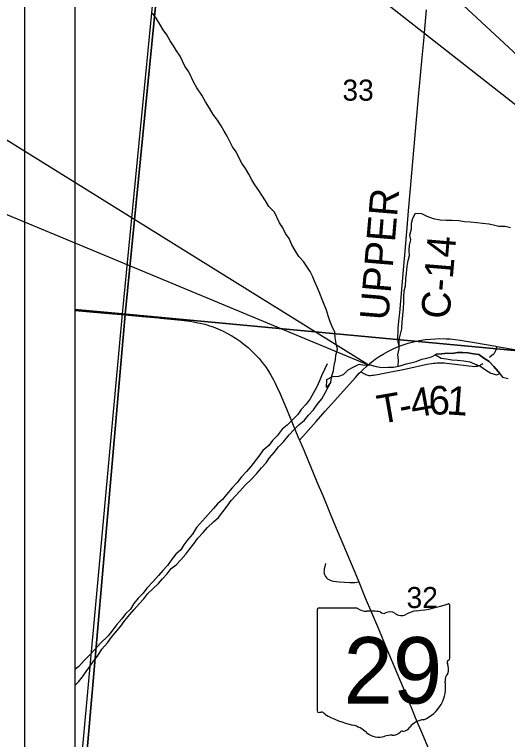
# Model space of a CAD drawing. Extents: x 831 to 1552, y 430 to 870.
# Drawn here: x 943.37 to 962.97, y 664.2 to 692.99 of the extents above; entities that cross this region are included whole.
import ezdxf

# ---------------------------------------------------------------- set-up
doc = ezdxf.new("R2010")
doc.units = 0
for name, color, linetype in [('GM_X_Corporation', 7, 'Continuous'), ('GM_X_County_Road', 7, 'Continuous'), ('GM_X_County_Road_Text', 7, 'Continuous'), ('GM_X_Major_River', 7, 'Continuous'), ('GM_X_Minor_Lake', 7, 'Continuous'), ('GM_X_Minor_River', 7, 'Continuous'), ('GM_X_Section_Text', 7, 'Continuous'), ('GM_X_State_Location', 7, 'Continuous'), ('GM_X_State_Route', 7, 'Continuous'), ('GM_X_State_Shield', 7, 'Continuous'), ('GM_X_Township_Road', 7, 'Continuous'), ('GM_X_Township_Road_Text', 7, 'Continuous'), ('SH_Data', 7, 'Continuous'), ('SH_Text', 7, 'Continuous')]:
    doc.layers.add(name, color=color, linetype=linetype)

msp = doc.modelspace()

# ---------------------------------------------------------------- linework, layer by layer
at = {"layer": 'GM_X_Corporation'}
msp.add_lwpolyline([(957.479, 781.045), (956.56, 771.006), (955.451, 760.717), (953.653, 740.871), (952.689, 730.885), (949.971, 703.401), (947.763, 681.071), (945.766, 658.183), (945.766, 650.938), (1069.909, 650.938), (1070.34, 654.531), (1072.813, 675.454), (1078.126, 715.958), (1081.227, 740.59), (1081.766, 744.853), (1081.766, 786.938)], dxfattribs=at)
for points in [[(945.766, 741.831), (945.766, 658.183), (947.763, 681.071), (949.971, 703.401), (952.689, 730.885), (953.653, 740.871)], [(945.766, 701.429), (945.766, 681.274), (947.656, 681.105), (949.612, 701.081)], [(970.228, 699.411), (968.2, 679.179), (947.656, 681.105), (949.612, 701.081)], [(945.766, 681.274), (945.766, 661.485), (945.863, 661.476), (947.656, 681.105)], [(947.656, 681.105), (968.2, 679.179), (966.669, 658.742), (945.863, 661.476)]]:
    msp.add_lwpolyline(points, close=True, dxfattribs=at)
at = {"layer": 'GM_X_County_Road'}
msp.add_lwpolyline([(958.663, 679.814), (958.644, 679.888), (958.633, 679.934), (958.623, 679.981), (958.615, 680.041), (958.61, 680.11), (958.607, 680.202), (958.614, 680.366), (958.625, 680.543), (958.66, 680.926), (958.681, 681.149), (958.72, 681.607), (958.833, 682.845), (958.897, 683.576), (958.94, 684.071), (958.98, 684.516), (959.037, 685.198), (959.116, 686.076), (959.195, 686.993), (959.313, 688.355), (959.435, 689.716), (959.511, 690.571), (959.576, 691.288), (959.636, 691.944), (959.689, 692.563), (959.744, 693.182)], dxfattribs=at)
at = {"layer": 'GM_X_Major_River'}
for points in [[(955.948, 678.394), (955.978, 678.644), (956.052, 678.84), (956.081, 679.053), (956.133, 679.272), (956.146, 679.462), (956.213, 679.696), (956.152, 679.926), (956.121, 680.163), (956.104, 680.369), (955.983, 680.631), (955.897, 680.824), (955.842, 681.023), (955.765, 681.246), (955.674, 681.478), (955.603, 681.677), (955.512, 681.916), (955.412, 682.132), (955.298, 682.402), (955.213, 682.595), (955.128, 682.787), (954.989, 682.982), (954.858, 683.184), (954.674, 683.387), (954.522, 683.62), (954.392, 683.844), (954.285, 684.091), (954.147, 684.3), (954.032, 684.524), (953.901, 684.718), (953.701, 685.135), (953.48, 685.37), (953.35, 685.595), (953.197, 685.812), (953.081, 686.006), (952.928, 686.223), (952.798, 686.425), (952.69, 686.649), (952.545, 686.874), (952.407, 687.091), (952.285, 687.315), (952.177, 687.531), (952.039, 687.741), (951.931, 687.941), (951.824, 688.158), (951.701, 688.359), (951.586, 688.575), (951.44, 688.793), (951.272, 689.018), (951.121, 689.274), (950.961, 689.522), (950.809, 689.785), (950.62, 690.079), (950.498, 690.288), (950.298, 690.72), (950.145, 690.937), (950.044, 691.138), (949.959, 691.331), (949.814, 691.548), (949.683, 691.742), (949.56, 691.951), (949.422, 692.183), (949.284, 692.384), (949.146, 692.601), (948.994, 692.849), (948.848, 693.043)], [(955.802, 679.114), (955.697, 678.896), (955.568, 678.641), (955.494, 678.438), (955.381, 678.205), (955.252, 677.973), (955.124, 677.733), (954.958, 677.51), (954.77, 677.302), (954.635, 677.101), (954.401, 676.879), (954.205, 676.68), (954.011, 676.518), (953.806, 676.265), (953.626, 676.073), (953.483, 675.879), (953.235, 675.681), (953.076, 675.449), (952.769, 675.047), (952.596, 674.847), (952.392, 674.632), (952.226, 674.409), (952.015, 674.194), (951.795, 673.934), (951.637, 673.733), (951.443, 673.564), (951.285, 673.371), (951.066, 673.133), (950.838, 672.881), (950.603, 672.614), (950.443, 672.36), (950.263, 672.145), (950.105, 671.936), (949.977, 671.734), (949.783, 671.565), (949.601, 671.327), (949.451, 671.11), (949.27, 670.91), (949.097, 670.71), (948.886, 670.472), (948.635, 670.213), (948.477, 670.013), (948.289, 669.813), (948.116, 669.597), (947.973, 669.373), (947.778, 669.196), (947.635, 668.987), (947.439, 668.772), (947.281, 668.556), (947.085, 668.318), (946.78, 668.015), (946.56, 667.778), (946.357, 667.563), (946.138, 667.333), (945.926, 667.104), (945.766, 666.974)], [(945.766, 666.339), (945.908, 666.487), (946.066, 666.688), (946.216, 666.905), (946.366, 667.098), (946.509, 667.307), (946.666, 667.508), (946.834, 667.785), (947.069, 668.044), (947.227, 668.26), (947.432, 668.513), (947.589, 668.706), (947.755, 668.922), (947.952, 669.168), (948.124, 669.361), (948.329, 669.591), (948.516, 669.783), (948.667, 669.999), (948.885, 670.198), (949.096, 670.39), (949.253, 670.583), (949.434, 670.784), (949.599, 670.992), (949.793, 671.138), (949.981, 671.331), (950.177, 671.561), (950.343, 671.777), (950.493, 671.97), (950.651, 672.194), (950.87, 672.416), (951.036, 672.624), (951.277, 672.846), (951.472, 673.022), (951.646, 673.246), (951.819, 673.461), (951.978, 673.693), (952.338, 674.078), (952.534, 674.3), (952.776, 674.529), (952.987, 674.744), (953.184, 674.982), (953.372, 675.182), (953.5, 675.391), (953.695, 675.598), (953.869, 675.822), (954.064, 676.021), (954.293, 676.296), (954.473, 676.497), (954.676, 676.696), (954.894, 676.88), (955.059, 677.073), (955.255, 677.296), (955.406, 677.504), (955.587, 677.727), (955.715, 677.96), (955.948, 678.394)]]:
    msp.add_lwpolyline(points, dxfattribs=at)
at = {"layer": 'GM_X_Minor_Lake'}
for points in [[(962.66, 678.735), (962.601, 678.814), (962.425, 679.017), (962.241, 679.213), (962.024, 679.341), (961.831, 679.484), (961.612, 679.513), (961.393, 679.55), (961.173, 679.564), (960.983, 679.562), (960.77, 679.53), (960.565, 679.544), (960.352, 679.52), (960.147, 679.503), (960.107, 679.482)], [(960.107, 679.482), (960.324, 679.338), (960.544, 679.316), (960.747, 679.272), (960.975, 679.258), (961.225, 679.243), (961.466, 679.198), (961.661, 679.116), (961.901, 679.01), (962.094, 678.882), (962.303, 678.747), (962.536, 678.686), (962.66, 678.735)]]:
    msp.add_lwpolyline(points, dxfattribs=at)
at = {"layer": 'GM_X_Minor_River'}
for points in [[(958.623, 679.028), (958.63, 679.266), (958.605, 679.473), (958.665, 679.714), (958.654, 680.088), (958.713, 680.292), (958.764, 680.503), (958.773, 680.792), (958.803, 681.035), (958.834, 681.316), (958.841, 681.559), (958.839, 681.765), (958.862, 682.015), (958.913, 682.211), (958.921, 682.5), (958.958, 682.712), (958.981, 682.978), (959.018, 683.221), (959.07, 683.425), (959.061, 683.63), (959.074, 683.835), (959.118, 684.04), (959.078, 684.231), (959.146, 684.473), (959.145, 684.701), (959.197, 684.905), (959.309, 685.107), (959.551, 685.092), (959.761, 684.987), (960.016, 684.888), (960.288, 684.835), (960.53, 684.82), (960.766, 684.828), (961.03, 684.805), (961.257, 684.776), (961.5, 684.761), (961.742, 684.731), (961.976, 684.701), (962.218, 684.679), (962.414, 684.635), (962.618, 684.591), (962.868, 684.583), (963.087, 684.531)], [(955.948, 678.394), (955.774, 678.179), (955.784, 678.49), (956.015, 678.621), (956.258, 678.629), (956.45, 678.691), (956.637, 678.884), (956.83, 678.985), (957.069, 679.099), (957.288, 679.07), (957.493, 679.079), (957.742, 679.011), (957.976, 678.974), (958.211, 678.982), (958.439, 678.99), (958.699, 679.044), (958.936, 679.113), (959.127, 679.16), (959.341, 679.207), (959.556, 679.3), (959.755, 679.347), (959.946, 679.395), (960.147, 679.503), (960.352, 679.52), (960.565, 679.544), (960.77, 679.53), (960.983, 679.562), (961.173, 679.564), (961.393, 679.55), (961.612, 679.513), (961.831, 679.484), (962.024, 679.341), (962.241, 679.213), (962.425, 679.017), (962.601, 678.814), (962.769, 678.588), (962.987, 678.536)]]:
    msp.add_lwpolyline(points, dxfattribs=at)
at = {"layer": 'GM_X_State_Route'}
for points in [[(945.766, 681.238), (946.953, 681.134), (947.767, 681.061)], [(947.767, 681.061), (948.437, 681), (949.094, 680.944), (949.172, 680.936)], [(949.172, 680.936), (949.583, 680.896), (950.009, 680.851), (950.342, 680.806), (950.486, 680.783), (950.662, 680.751), (950.764, 680.73), (950.869, 680.705), (950.932, 680.689), (951.014, 680.667), (951.121, 680.633), (951.262, 680.584), (951.353, 680.549), (951.448, 680.511), (951.55, 680.465), (951.643, 680.423), (951.831, 680.329), (952.005, 680.231), (952.185, 680.118), (952.339, 680.012), (952.498, 679.891), (952.652, 679.764), (952.809, 679.622), (952.951, 679.481), (953.093, 679.324), (953.22, 679.169), (953.34, 679.01), (953.465, 678.823), (953.555, 678.674), (953.664, 678.477), (953.728, 678.354), (953.786, 678.232), (953.925, 677.925), (954.177, 677.33), (954.297, 677.043), (954.635, 676.234), (954.697, 676.092)], [(954.697, 676.092), (954.83, 676.231), (955.357, 676.825), (955.722, 677.233), (956.338, 677.933), (956.921, 678.578), (957.075, 678.741), (957.131, 678.796), (957.208, 678.873), (957.402, 679.049), (957.573, 679.194), (957.712, 679.3), (957.867, 679.406), (958.026, 679.505), (958.234, 679.618), (958.447, 679.722), (958.63, 679.802), (958.663, 679.814), (958.817, 679.872), (959.019, 679.938), (959.224, 679.991), (959.469, 680.042), (959.69, 680.078), (959.901, 680.102), (960.1, 680.116), (960.263, 680.12), (960.524, 680.116), (960.692, 680.105), (960.885, 680.089), (961.083, 680.063), (961.66, 679.969), (962.505, 679.82), (962.551, 679.812), (963.384, 679.658)], [(954.697, 676.092), (954.877, 675.664), (955.392, 674.43), (955.619, 673.891), (956.055, 672.848), (956.891, 670.841), (957.051, 670.46), (957.314, 669.832), (957.566, 669.238), (957.834, 668.596), (958.101, 667.94), (958.816, 666.248), (959.172, 665.375), (959.299, 665.078), (959.582, 664.402), (959.887, 663.668), (960.221, 662.865), (960.529, 662.132), (960.961, 661.087), (961.295, 660.284), (961.456, 659.9)]]:
    msp.add_lwpolyline(points, dxfattribs=at)
at = {"layer": 'GM_X_State_Shield'}
for p, q in [((956.994, 669.418), (955.45, 669.418)), ((960.671, 667.424), (960.671, 669.517)), ((955.398, 669.349), (955.398, 665.347)), ((960.67, 667.424), (960.671, 667.424))]:
    msp.add_line(p, q, dxfattribs=at)
for centre, radius, start, end in [((955.458, 669.358), 0.0611, 98.1301, 188.1301), ((957.362, 669.883), 0.593, 231.6195, 271.1119), ((958.793, 674.875), 5.592, 275.8445, 288.9065), ((960.613, 669.526), 0.0587, 351.8621, 97.738), ((957.558, 667.171), 2.127, 80.4867, 94.9883), ((958.041, 669.379), 0.171, 219.7921, 297.1024), ((958.292, 668.916), 0.355, 54.4667, 119.1411), ((958.751, 669.55), 0.428, 233.8562, 294.8282), ((959.506, 668.196), 1.125, 97.3462, 120.7689), ((960.608, 667.415), 0.0628, 289.6038, 7.7341), ((960.657, 667.27), 0.0909, 107.944, 210.337), ((960.079, 667.005), 0.545, 340.033, 23.6496), ((960.881, 666.547), 0.397, 136.8065, 186.9296), ((959.106, 666.281), 1.399, 292.3089, 8.9858), ((955.459, 665.338), 0.0616, 171.9584, 258.3066), ((955.468, 665.748), 0.47, 267.339, 280.6039), ((955.564, 665.116), 0.17, 29.7484, 93.2717), ((957.705, 668.712), 4.038, 240.4129, 257.1985), ((959.696, 664.223), 0.766, 94.4031, 142.5768), ((956.501, 663.549), 1.264, 47.1842, 75.836), ((958.39, 664.796), 0.427, 268.777, 315.5493), ((958.776, 664.409), 0.12, 65.7517, 132.6484), ((958.725, 664.959), 0.452, 282.8732, 323.2771), ((957.868, 665.096), 0.802, 230.7004, 286.2918), ((958.331, 663.712), 0.659, 85.6951, 111.2099)]:
    msp.add_arc(centre, radius, start, end, dxfattribs=at)
at = {"layer": 'GM_X_Township_Road'}
for points in [[(962.252, 679.385), (962.36, 679.47), (962.417, 679.52), (962.437, 679.539), (962.458, 679.567), (962.476, 679.595), (962.49, 679.62), (962.503, 679.65), (962.517, 679.691), (962.532, 679.745), (962.551, 679.812)], [(957.131, 678.796), (957.249, 678.736), (957.311, 678.705), (957.364, 678.681), (957.411, 678.667), (957.448, 678.66), (957.482, 678.657), (957.522, 678.657), (957.584, 678.663), (957.645, 678.671), (957.804, 678.698), (958.196, 678.768), (958.819, 678.89), (959.243, 678.982), (959.474, 679.035), (959.777, 679.101), (959.948, 679.132), (960.023, 679.142), (960.096, 679.15), (960.16, 679.155), (960.222, 679.158), (960.283, 679.158), (960.357, 679.156), (960.444, 679.152), (960.543, 679.145), (960.889, 679.109), (961.432, 679.041), (961.579, 679.023), (961.666, 679.018), (961.708, 679.02), (961.74, 679.023), (961.768, 679.027), (961.801, 679.035), (961.848, 679.051), (961.889, 679.071), (961.925, 679.091), (961.987, 679.132)], [(955.725, 671.19), (955.681, 670.959), (955.672, 670.904), (955.667, 670.862), (955.672, 670.819), (955.681, 670.786), (955.693, 670.753), (955.703, 670.732), (955.712, 670.711), (955.732, 670.673), (955.745, 670.655), (955.77, 670.619), (955.812, 670.58), (955.865, 670.548), (955.92, 670.523), (955.979, 670.504), (956.052, 670.488), (956.15, 670.473), (956.272, 670.463), (956.699, 670.432), (956.816, 670.429), (956.9, 670.433), (956.975, 670.447), (957.051, 670.46)]]:
    msp.add_lwpolyline(points, dxfattribs=at)
at = {"layer": 'SH_Data'}
for p, q in [((943.766, 788.938), (943.766, 648.938)), ((945.766, 786.938), (945.766, 650.938))]:
    msp.add_line(p, q, dxfattribs=at)
at = {"layer": 'SH_Text'}
for points in [[(977.418, 678.354), (911.466, 739.393), (911.466, 729.958)], [(957.434, 679.077), (911.466, 707.618), (911.466, 698.183)]]:
    msp.add_lwpolyline(points, close=True, dxfattribs=at)

# ---------------------------------------------------------------- texts
at = {"layer": 'GM_X_County_Road_Text'}
for s, rotation, p in [('UPPER', 85.1629, (958.225, 680.819)), ('C-14', 85.2082, (960.655, 680.871))]:
    msp.add_text(s, height=1.1364, rotation=rotation, dxfattribs=at).set_placement(p)
at = {"layer": 'GM_X_Section_Text'}
for s, p in [('33', (956.404, 689.569)), ('32', (958.954, 669.419))]:
    msp.add_text(s, height=0.8371, rotation=0, dxfattribs=at).set_placement(p)
at = {"layer": 'GM_X_State_Location'}
for s in ['s', 'r']:
    msp.add_text(s, height=0.00379, dxfattribs=at).set_placement((957.975, 667.082))
msp.add_text('29', height=0.00379, rotation=0, dxfattribs=at).set_placement((957.021, 666.806))
at = {"layer": 'GM_X_State_Shield'}
msp.add_text('29', height=2.6367, dxfattribs=at).set_placement((956.45, 665.629))
at = {"layer": 'GM_X_Township_Road_Text'}
for s, rotation, p in [('4', 10.1066, (959.205, 676.964)), ('6', 2.8164, (959.856, 677.083)), ('1', 355.901, (960.519, 677.117)), ('T', 9.8759, (957.891, 676.726)), ('-', 10.9475, (958.751, 676.876))]:
    msp.add_text(s, height=1.136, rotation=rotation, dxfattribs=at).set_placement(p)

doc.saveas('drawing.dxf')
